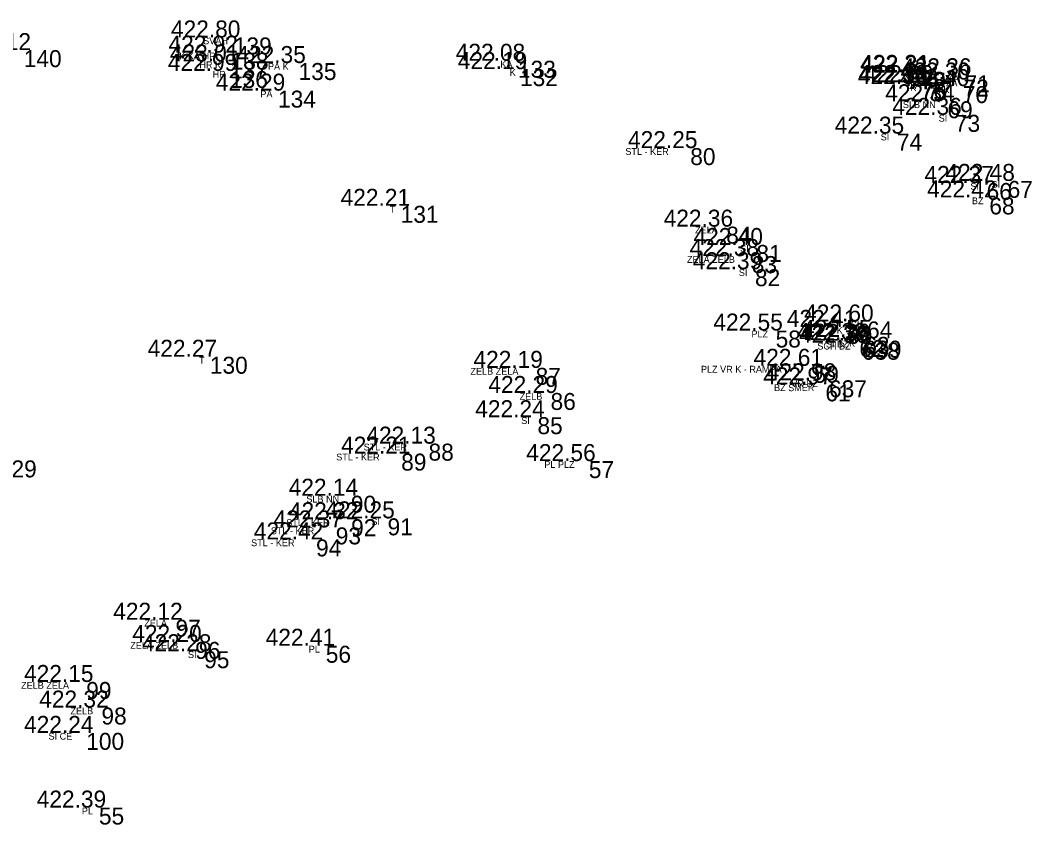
# Model space of a CAD drawing. Extents: x -639373 to -639057, y -1138651 to -1138359.
# Drawn here: x -639101.43 to -639056.75, y -1138641.52 to -1138605.97 of the extents above; entities that cross this region are included whole.
import ezdxf

# ---------------------------------------------------------------- set-up
doc = ezdxf.new("R2010")
doc.units = 0
for name, color, linetype in [('Vrstva 11', 7, 'Continuous'), ('Vrstva 12', 7, 'Continuous'), ('Vrstva 13', 7, 'Continuous'), ('Vrstva 14', 7, 'Continuous'), ('Vrstva 57', 7, 'Continuous')]:
    doc.layers.add(name, color=color, linetype=linetype)

msp = doc.modelspace()

# ---------------------------------------------------------------- linework, layer by layer
at = {"layer": 'Vrstva 11'}
for p, q in [((-639092.27, -1138606.73), (-639092.27, -1138606.73)), ((-639092.41, -1138607.4), (-639092.41, -1138607.4)), ((-639092.44, -1138607.79), (-639092.44, -1138607.79)), ((-639089.41, -1138607.86), (-639089.41, -1138607.86)), ((-639079.72, -1138607.76), (-639079.72, -1138607.76)), ((-639092.44, -1138608.21), (-639092.44, -1138608.21)), ((-639079.63, -1138608.13), (-639079.63, -1138608.13)), ((-639061.95, -1138608.25), (-639061.95, -1138608.25)), ((-639061.93, -1138608.28), (-639061.93, -1138608.28)), ((-639059.99, -1138608.4), (-639059.99, -1138608.4)), ((-639061.94, -1138608.79), (-639061.94, -1138608.79)), ((-639061.93, -1138608.7), (-639061.93, -1138608.7)), ((-639061.66, -1138608.71), (-639061.66, -1138608.71)), ((-639060.04, -1138608.59), (-639060.04, -1138608.59)), ((-639090.32, -1138609.08), (-639090.32, -1138609.08)), ((-639060.07, -1138608.88), (-639060.07, -1138608.88)), ((-639060.75, -1138609.55), (-639060.75, -1138609.55)), ((-639060.42, -1138610.15), (-639060.42, -1138610.15)), ((-639062.98, -1138610.98), (-639062.98, -1138610.98)), ((-639072.11, -1138611.62), (-639072.11, -1138611.62)), ((-639059.02, -1138613.16), (-639059.02, -1138613.16)), ((-639058.09, -1138613.07), (-639058.09, -1138613.07)), ((-639084.9, -1138614.17), (-639084.9, -1138614.17)), ((-639058.9, -1138613.8), (-639058.9, -1138613.8)), ((-639070.52, -1138615.09), (-639070.52, -1138615.09)), ((-639069.19, -1138615.9), (-639069.19, -1138615.9)), ((-639069.39, -1138616.39), (-639069.39, -1138616.39)), ((-639069.25, -1138616.97), (-639069.25, -1138616.97)), ((-639065.19, -1138619.52), (-639065.19, -1138619.52)), ((-639064.3, -1138619.28), (-639064.3, -1138619.28)), ((-639068.34, -1138619.68), (-639068.34, -1138619.68)), ((-639064.42, -1138619.96), (-639064.42, -1138619.96)), ((-639064.64, -1138620.1), (-639064.64, -1138620.1)), ((-639064.53, -1138620.22), (-639064.53, -1138620.22)), ((-639064.45, -1138620.13), (-639064.45, -1138620.13)), ((-639093.33, -1138620.84), (-639093.33, -1138620.84)), ((-639078.94, -1138621.33), (-639078.94, -1138621.33)), ((-639066.66, -1138621.24), (-639066.66, -1138621.24)), ((-639066.14, -1138622.06), (-639066.14, -1138622.06)), ((-639065.98, -1138621.88), (-639065.98, -1138621.88)), ((-639078.28, -1138622.44), (-639078.28, -1138622.44)), ((-639078.86, -1138623.51), (-639078.86, -1138623.51)), ((-639083.67, -1138624.68), (-639083.67, -1138624.68)), ((-639084.88, -1138625.12), (-639084.88, -1138625.12)), ((-639076.59, -1138625.45), (-639076.59, -1138625.45)), ((-639087.1, -1138626.98), (-639087.1, -1138626.98)), ((-639087.09, -1138628.02), (-639087.09, -1138628.02)), ((-639085.48, -1138627.98), (-639085.48, -1138627.98)), ((-639087.77, -1138628.38), (-639087.77, -1138628.38)), ((-639088.64, -1138628.91), (-639088.64, -1138628.91)), ((-639094.85, -1138632.46), (-639094.85, -1138632.46)), ((-639093.98, -1138633.44), (-639093.98, -1138633.44)), ((-639093.58, -1138633.85), (-639093.58, -1138633.85)), ((-639088.21, -1138633.61), (-639088.21, -1138633.61)), ((-639098.79, -1138635.21), (-639098.79, -1138635.21)), ((-639098.12, -1138636.34), (-639098.12, -1138636.34)), ((-639098.79, -1138637.46), (-639098.79, -1138637.46)), ((-639098.23, -1138640.76), (-639098.23, -1138640.76))]:
    msp.add_line(p, q, dxfattribs=at)

# ---------------------------------------------------------------- texts
at = {"layer": 'Vrstva 12'}
for s, p in [('422.80 ', (-639094.769, -1138606.73)), ('422.92 ', (-639094.879, -1138607.4)), ('423.01 ', (-639094.815, -1138607.79)), ('422.08 ', (-639082.189, -1138607.76)), ('422.99 ', (-639094.909, -1138608.21)), ('422.35 ', (-639091.88, -1138607.86)), ('422.19 ', (-639082.099, -1138608.13)), ('422.31 ', (-639064.325, -1138608.25)), ('422.31 ', (-639064.305, -1138608.28)), ('422.33 ', (-639064.399, -1138608.7)), ('422.30 ', (-639064.159, -1138608.71)), ('422.30 ', (-639062.539, -1138608.59)), ('422.36 ', (-639062.476, -1138608.4)), ('422.29 ', (-639092.789, -1138609.08)), ('422.36 ', (-639064.426, -1138608.79)), ('422.40 ', (-639062.569, -1138608.88)), ('422.34 ', (-639063.219, -1138609.55)), ('422.36 ', (-639062.906, -1138610.15)), ('422.35 ', (-639065.45, -1138610.98)), ('422.25 ', (-639074.58, -1138611.62)), ('422.37 ', (-639061.489, -1138613.16)), ('422.48 ', (-639060.559, -1138613.07)), ('422.42 ', (-639061.369, -1138613.8)), ('422.21 ', (-639087.275, -1138614.17)), ('422.36 ', (-639073.006, -1138615.09)), ('422.40 ', (-639071.689, -1138615.9)), ('422.38 ', (-639071.859, -1138616.39)), ('422.39 ', (-639071.719, -1138616.97)), ('422.60 ', (-639066.799, -1138619.28)), ('422.55 ', (-639070.81, -1138619.68)), ('422.41 ', (-639067.565, -1138619.52)), ('422.39 ', (-639067.109, -1138620.1)), ('422.30 ', (-639067.029, -1138620.22)), ('422.30 ', (-639066.949, -1138620.13)), ('422.55 ', (-639066.89, -1138619.96)), ('422.27 ', (-639095.799, -1138620.84)), ('422.61 ', (-639069.035, -1138621.24)), ('422.19 ', (-639081.409, -1138621.33)), ('422.97 ', (-639068.609, -1138622.06)), ('422.98 ', (-639068.449, -1138621.88)), ('422.29 ', (-639080.749, -1138622.44)), ('422.24 ', (-639081.329, -1138623.51)), ('422.13 ', (-639086.139, -1138624.68)), ('422.21 ', (-639087.255, -1138625.12)), ('422.56 ', (-639079.076, -1138625.45)), ('422.14 ', (-639089.569, -1138626.98)), ('422.37 ', (-639090.239, -1138628.38)), ('422.32 ', (-639089.559, -1138628.02)), ('422.25 ', (-639087.95, -1138627.98)), ('422.42 ', (-639091.109, -1138628.91)), ('422.12 ', (-639097.319, -1138632.46)), ('422.20 ', (-639096.479, -1138633.44)), ('422.41 ', (-639090.585, -1138633.61)), ('422.28 ', (-639096.049, -1138633.85)), ('422.15 ', (-639101.26, -1138635.21)), ('422.32 ', (-639100.589, -1138636.34)), ('422.24 ', (-639101.259, -1138637.46)), ('422.39 ', (-639100.699, -1138640.76))]:
    msp.add_text(s, height=0.75, dxfattribs=at).set_placement(p)
at = {"layer": 'Vrstva 13'}
for s, p in [(' 139', (-639092.27, -1138607.48)), (' 140', (-639101.55, -1138608.04)), (' 138', (-639092.41, -1138608.15)), (' 137', (-639092.44, -1138608.54)), (' 135', (-639089.41, -1138608.61)), (' 133', (-639079.72, -1138608.51)), (' 136', (-639092.44, -1138608.96)), (' 132', (-639079.63, -1138608.88)), (' 78', (-639061.95, -1138609)), (' 79', (-639061.93, -1138609.03)), (' 71', (-639059.99, -1138609.15)), (' 75', (-639061.94, -1138609.54)), (' 76', (-639061.93, -1138609.45)), (' 77', (-639061.66, -1138609.46)), (' 70', (-639060.07, -1138609.63)), (' 72', (-639060.04, -1138609.34)), (' 134', (-639090.32, -1138609.83)), (' 69', (-639060.75, -1138610.3)), (' 73', (-639060.42, -1138610.9)), (' 74', (-639062.98, -1138611.73)), (' 80', (-639072.11, -1138612.37)), (' 66', (-639059.02, -1138613.91)), (' 67', (-639058.09, -1138613.82)), (' 68', (-639058.9, -1138614.55)), (' 131', (-639084.9, -1138614.92)), (' 84', (-639070.52, -1138615.84)), (' 81', (-639069.19, -1138616.65)), (' 83', (-639069.39, -1138617.14)), (' 82', (-639069.25, -1138617.72)), (' 60', (-639065.19, -1138620.27)), (' 64', (-639064.3, -1138620.03)), (' 58', (-639068.34, -1138620.43)), (' 63', (-639064.42, -1138620.71)), (' 62', (-639064.64, -1138620.85)), (' 638', (-639064.53, -1138620.97)), (' 639', (-639064.45, -1138620.88)), (' 130', (-639093.33, -1138621.59)), (' 87', (-639078.94, -1138622.08)), (' 59', (-639066.66, -1138621.99)), (' 61', (-639066.14, -1138622.81)), (' 637', (-639065.98, -1138622.63)), (' 86', (-639078.28, -1138623.19)), (' 85', (-639078.86, -1138624.26)), (' 88', (-639083.67, -1138625.43)), (' 89', (-639084.88, -1138625.87)), (' 129', (-639102.65, -1138626.17)), (' 57', (-639076.59, -1138626.2)), (' 90', (-639087.1, -1138627.73)), (' 92', (-639087.09, -1138628.77)), (' 91', (-639085.48, -1138628.73)), (' 93', (-639087.77, -1138629.13)), (' 94', (-639088.64, -1138629.66)), (' 97', (-639094.85, -1138633.21)), (' 96', (-639093.98, -1138634.19)), (' 95', (-639093.58, -1138634.6)), (' 56', (-639088.21, -1138634.36)), (' 99', (-639098.79, -1138635.96)), (' 98', (-639098.12, -1138637.09)), (' 100', (-639098.79, -1138638.21)), (' 55', (-639098.23, -1138641.51))]:
    msp.add_text(s, height=0.75, dxfattribs=at).set_placement(p)
at = {"layer": 'Vrstva 14'}
msp.add_text('423.12 ', height=0.75, dxfattribs=at).set_placement((-639104.019, -1138607.29))
at = {"layer": 'Vrstva 57'}
for s, p in [('SVAH', (-639093.345, -1138607.03)), ('K KA HR', (-639094.399, -1138607.7)), ('HR K', (-639093.515, -1138608.09)), ('PA K', (-639090.485, -1138608.16)), ('KA', (-639080.22, -1138608.06)), ('HR', (-639092.929, -1138608.51)), ('K', (-639079.805, -1138608.43)), ('KA', (-639062.45, -1138608.55)), ('KA', (-639062.43, -1138608.58)), ('KA', (-639060.49, -1138608.7)), ('ZA', (-639062.16, -1138609.01)), ('K', (-639062.115, -1138609.09)), ('K', (-639062.105, -1138609)), ('SI K', (-639061.145, -1138609.18)), ('ZA', (-639060.54, -1138608.89)), ('PA', (-639090.82, -1138609.38)), ('SLB NN', (-639062.439, -1138609.85)), ('SI', (-639060.858, -1138610.45)), ('SI', (-639063.418, -1138611.28)), ('STL - KER', (-639074.699, -1138611.92)), ('SI', (-639059.458, -1138613.46)), ('SI', (-639058.528, -1138613.37)), ('T', (-639085.1, -1138614.47)), ('BZ', (-639059.389, -1138614.1)), ('ZELA', (-639071.62, -1138615.39)), ('SI', (-639069.628, -1138616.2)), ('ZELA ZELB', (-639071.979, -1138616.69)), ('SI', (-639069.688, -1138617.27)), ('K', (-639065.365, -1138619.82)), ('SI', (-639064.738, -1138619.58)), ('PLZ', (-639069.129, -1138619.98)), ('SI', (-639064.858, -1138620.26)), ('SCH BZ', (-639066.219, -1138620.52)), ('SI BZ', (-639065.839, -1138620.43)), ('K', (-639064.815, -1138620.4)), ('T', (-639093.53, -1138621.14)), ('ZELB ZELA', (-639081.54, -1138621.63)), ('PLZ VR K - RAMPA', (-639071.36, -1138621.54)), ('BZ SMER', (-639068.129, -1138622.36)), ('VR BZ', (-639067.369, -1138622.18)), ('ZELB', (-639079.369, -1138622.74)), ('SI', (-639079.298, -1138623.81)), ('STL - KER', (-639086.259, -1138624.98)), ('STL - KER', (-639087.469, -1138625.42)), ('PL PLZ', (-639078.279, -1138625.75)), ('SLB NN', (-639088.789, -1138627.28)), ('STL - KER', (-639089.679, -1138628.32)), ('SI', (-639085.918, -1138628.28)), ('STL - KER', (-639090.359, -1138628.68)), ('STL - KER', (-639091.229, -1138629.21)), ('ZELA', (-639095.95, -1138632.76)), ('ZELA ZELB', (-639096.569, -1138633.74)), ('SI', (-639094.018, -1138634.15)), ('PL', (-639088.685, -1138633.91)), ('ZELB ZELA', (-639101.39, -1138635.51)), ('ZELB', (-639099.209, -1138636.64)), ('SI CE', (-639100.177, -1138637.76)), ('PL', (-639098.705, -1138641.06))]:
    msp.add_text(s, height=0.3, dxfattribs=at).set_placement(p)

doc.saveas('drawing.dxf')
